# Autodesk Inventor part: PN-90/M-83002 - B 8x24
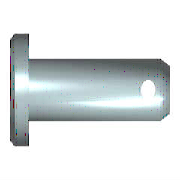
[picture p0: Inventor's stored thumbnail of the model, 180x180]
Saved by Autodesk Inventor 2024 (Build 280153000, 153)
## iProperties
Company: ATC
IsCustomPart: 0
Created: 2023-03
Part Number: PN-90/M-83002 - B 8x24
Material: Stal, miękka
Description: Sworznie z łbem
Document SubType Name: Modeling
Standard: PN-90/M-83002
Designer: Andrzej Jaskulski
Standards Organization: PN
Language: pl-PL
Size Designation: B 8x24
Categories: <MemberInstance><Categories><Category DisplayName="Mocowania" InternalName="e4da775c-781d-43d5-af7c-5136215cf5a6" Mnemonic="FSTN"><Category DisplayName="Kołki"
Density: 7.85 g/cm^3
Appearance: Częściowo polerowany
Checked By: A.J.
Engr Approved By: Andrzej Jaskulski
Mfg Approved By: Andrzej Jaskulski
Authority: A.J.
Author: Andrzej Jaskulski
Title: A.J.: Kurs R2024-MEP
Revision Number: 1/24
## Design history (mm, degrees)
revolve "Bryła" stored, may be unused: angle "d4" = 90 deg
sketch "Szkic1"
  geometry: L1 (-3, 0)-(-3, 7); L2 (-3, 7)-(0, 7); L3 (0, 7)-(0, 4); L4 (0, 4)-(24, 4); L5 (24, 4)-(24, 0); L6 (-3, 0)-(24, 0); L7 (-8.4, 0)-(29.4, 0) reference; L8 (0, -2.6)-(0, 8.6) reference; C1 r 1 at (20.5, 0)
  constraints: 12 end point, 3 parallel, 2 collinear, 2 perpendicular, 1 centre point, 1 point on line, 1 vertical
  dimensions: "d0" = 8 diameter of L4 L6 (= NND); "d1" = 14 diameter of L2 L6 (= KOD); "d2" = 3 distance of L1.end L2.end (= KOH); "d3" = 24 distance of L3.end L4.end (= NLG); "d5" = 3.5 distance from line of L5 C1.centre (= DIST); "d6" = 2 diameter of C1 (= BOR)
extrude "Otwór" cut sketch "Szkic1" extent not by distance; stored distance "d7" = 8 (= NND); taper "d8" = 0 deg
workaxis "Work Axis1"
workplane "Work Plane1"
node "Bryła1"
node "Korpusy bryłowe"
node "Korpusy powierzchniowe"
chamfer "Faza1" distance "d9" = 1 (= PHH2); stored, may be unused: angle "d10" = 45 deg (= FAWI2), second distance "d16" = 1 (= PHH2)
chamfer "Faza2" distance "d11" = 2 (= PHH1); stored, may be unused: angle "d12" = 30 deg (= FAWI1), second distance "d17" = 2 (= PHH1)
other parameters: "PHH1" = 2 [user parameter; used in 2 equation terms], "PHH2" = 1 [user parameter; used in 2 equation terms], "KOD" = 14 [user parameter; used in 1 equation term], "KOH" = 3 [user parameter; used in 1 equation term], "NND" = 8 [user parameter; used in 2 equation terms], "FAWI1" = 30 deg [user parameter; used in 1 equation term], "FAWI2" = 45 deg [user parameter; used in 1 equation term], "DIST" = 3.5 [user parameter; used in 1 equation term], "BOR" = 2 [user parameter; used in 1 equation term], "NLG" = 24 [user parameter; used in 1 equation term], "d13" = 0, "d14" = 0, "d27" = 0, "d28" = 0, "d29" = 0, "d30" = 0, "d31" = 0
